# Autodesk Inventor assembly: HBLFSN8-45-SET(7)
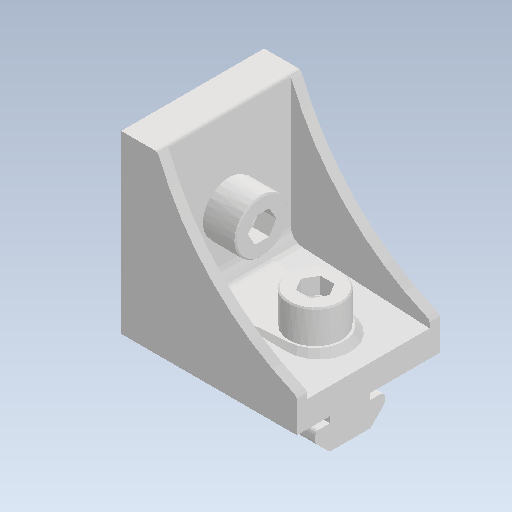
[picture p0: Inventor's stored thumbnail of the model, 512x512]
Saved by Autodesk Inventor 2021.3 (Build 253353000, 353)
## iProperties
Created: 2022-02
Part Number: HBLFSN8-45-SET(7)
Document SubType Name: Assembly
Designer: kengo
Author: kengo
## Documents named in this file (4)
- C:\Users\kengo\Documents\S2S_frame\SDC345\frame_misumi_ver12\HBLFSN8-45-SET(7).iam
- C:\Users\kengo\Documents\S2S_frame\SDC345\frame_misumi_ver12\HBLFSN8-45.ipt
- C:\Users\kengo\Documents\S2S_frame\SDC345\frame_misumi_ver12\HNTT8-8.ipt
- C:\Users\kengo\Documents\S2S_frame\SDC345\frame_misumi_ver12\CBM8-20.ipt
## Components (5 placed, 3 different names)
1. HBLFSN8-45
2. HNTT8-8
3. CBM8-20
4. HNTT8-8:1
5. CBM8-20:1
